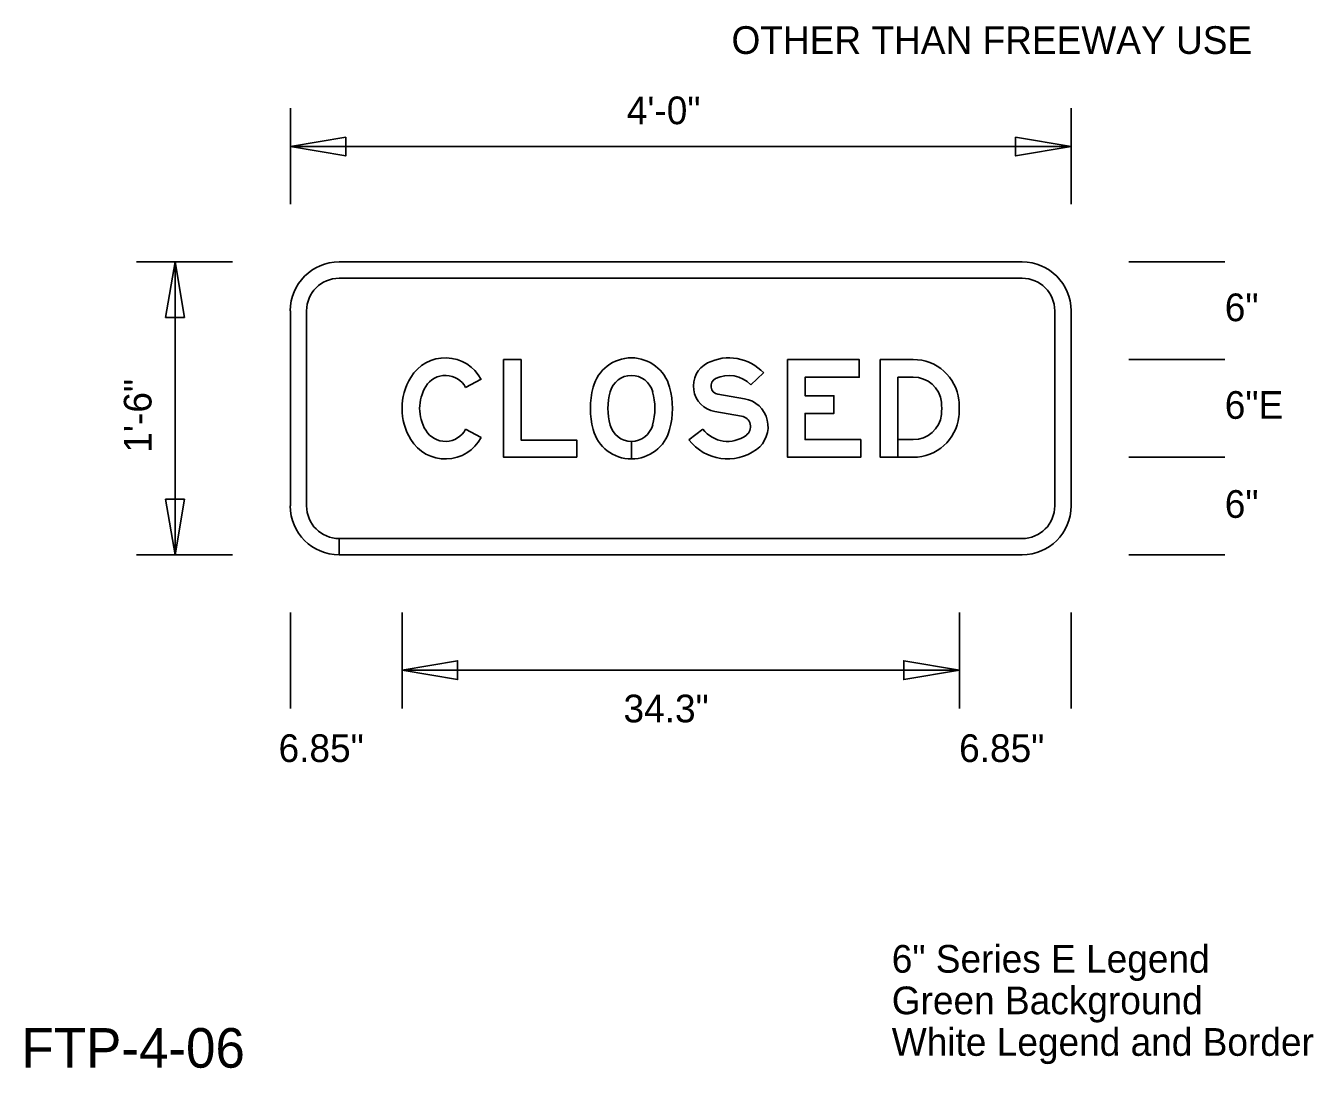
# Model space of a CAD drawing. Extents: x 0 to 770, y 0 to 495.
# Drawn here: x 584.7 to 747.4, y 356 to 487.7 of the extents above; entities that cross this region are included whole.
import ezdxf

# ---------------------------------------------------------------- set-up
doc = ezdxf.new("R2010")
doc.units = 0
for name, color, linetype in [('Dimension', 7, 'Continuous'), ('GSBWFill', 7, 'Continuous'), ('GSColorFill', 7, 'Continuous'), ('GSDims', 7, 'Continuous'), ('GSOutline', 7, 'Continuous'), ('TextStructures', 7, 'Continuous')]:
    doc.layers.add(name, color=color, linetype=linetype)

msp = doc.modelspace()

# ---------------------------------------------------------------- linework, layer by layer
at = {"layer": 'Dimension'}
for points in [[(618.12, 472.41), (625.13, 471.22), (625.13, 473.59)], [(716.78, 472.41), (709.76, 473.59), (709.76, 471.22)], [(603.55, 457.84), (602.36, 450.82), (604.74, 450.82)], [(603.55, 420.84), (604.74, 427.86), (602.36, 427.86)], [(632.24, 406.27), (639.25, 405.08), (639.25, 407.46)], [(702.66, 406.27), (695.64, 407.46), (695.64, 405.08)]]:
    msp.add_lwpolyline(points, close=True, dxfattribs=at)
at = {"layer": 'GSBWFill'}
for p, q in [((710.61, 457.84), (624.28, 457.84)), ((710.61, 457.84), (624.28, 457.84)), ((624.28, 455.78), (710.61, 455.78)), ((618.12, 451.67), (618.12, 427.01)), ((618.12, 451.67), (618.12, 427.01)), ((620.17, 427.01), (620.17, 451.67)), ((714.72, 451.67), (714.72, 427.01)), ((716.78, 427.01), (716.78, 451.67)), ((716.78, 427.01), (716.78, 451.67)), ((640.27, 441.96), (642.23, 443.01)), ((676.3, 442.3), (677.93, 443.81)), ((675.5, 440.56), (672.14, 441.12)), ((671.77, 438.94), (675.13, 438.37)), ((642.23, 435.67), (640.27, 436.71)), ((640.27, 436.71), (640.27, 436.71)), ((670.25, 436.71), (668.49, 435.36)), ((661.22, 432.96), (661.22, 435.18)), ((661.22, 435.18), (661.22, 432.96)), ((694.89, 433.17), (696.84, 433.17)), ((624.28, 420.84), (624.28, 422.89)), ((710.61, 422.89), (624.3, 422.89)), ((624.3, 422.89), (624.3, 420.84)), ((624.28, 420.84), (710.61, 420.84)), ((624.3, 420.84), (710.61, 420.84))]:
    msp.add_line(p, q, dxfattribs=at)
for points in [[(654.31, 433.17), (654.31, 435.33), (647.28, 435.33), (647.28, 445.5), (645.06, 445.5), (645.06, 433.17)], [(690.2, 435.39), (683.17, 435.39), (683.17, 438.71), (686.81, 438.71), (686.81, 440.93), (683.17, 440.93), (683.17, 443.28), (690.02, 443.28), (690.02, 445.5), (680.95, 445.5), (680.95, 433.17), (690.2, 433.17)]]:
    msp.add_lwpolyline(points, close=True, dxfattribs=at)
for points in [[(696.84, 445.5), (692.67, 445.5), (692.67, 433.17), (694.89, 433.17), (694.89, 443.28), (696.84, 443.28)], [(696.84, 435.39), (694.89, 435.39), (694.89, 433.17)]]:
    msp.add_lwpolyline(points, dxfattribs=at)
for centre, radius, start, end in [((624.28, 451.67), 6.17, 90, 180), ((624.28, 451.67), 6.17, 90, 180), ((710.61, 451.67), 6.17, 0, 90), ((710.61, 451.67), 6.17, 0, 90), ((624.28, 451.67), 4.11, 90, 180), ((710.61, 451.67), 4.11, 0, 90), ((637.71, 440.6), 5.12, 28.0265, 148.7499), ((661.22, 440.72), 5, 14.9618, 165.0382), ((672.32, 442.16), 3.27, 116.9123, 260.4087), ((673.55, 439.74), 5.98, 42.8759, 116.9123), ((639.79, 439.34), 7.55, 148.7499, 211.2501), ((637.71, 440.6), 2.9, 28.0265, 148.7499), ((661.22, 440.72), 2.78, 14.9618, 165.0382), ((672.32, 442.16), 1.05, 116.9123, 260.4087), ((673.55, 439.74), 3.76, 42.8759, 116.9123), ((639.79, 439.34), 5.33, 148.7499, 211.2501), ((666.4, 439.34), 10.36, 165.0382, 194.9618), ((666.4, 439.34), 8.14, 165.0382, 194.9618), ((656.04, 439.34), 8.14, 345.0382, 14.9618), ((656.04, 439.34), 10.36, 345.0382, 14.9618), ((674.91, 437.03), 3.58, 306.123, 80.4087), ((674.91, 437.03), 1.36, 306.123, 80.4087), ((637.71, 438.07), 2.9, 211.2501, 331.9735), ((661.22, 437.95), 5, 194.9618, 270), ((661.22, 437.95), 2.78, 194.9618, 270), ((661.22, 437.95), 2.78, 270.0127, 345.0382), ((661.22, 437.95), 5, 270.0071, 345.0382), ((673.38, 439.12), 3.95, 217.5895, 306.123), ((637.71, 438.07), 5.12, 211.2501, 331.9735), ((673.38, 439.12), 6.17, 217.5895, 306.123), ((624.28, 427.01), 6.17, 180, 270), ((624.28, 427.01), 6.17, 180, 270), ((624.28, 427.01), 4.11, 180, 270), ((710.61, 427.01), 6.17, 270, 0), ((710.61, 427.01), 4.11, 270, 0), ((710.61, 427.01), 6.17, 270, 0)]:
    msp.add_arc(centre, radius, start, end, dxfattribs=at)
for centre, major_axis, start_param, end_param in [((696.84, 439.71), (0, 5.8), 4.82584, 6.283185), ((696.84, 439.71), (0, 3.58), 4.82584, 6.283185), ((693.59, 439.34), (0, 6.84), 4.598938, 4.82584), ((693.59, 439.34), (0, 9.06), 4.598938, 4.82584), ((696.84, 438.97), (0, 3.58), 3.141593, 4.598938), ((696.84, 438.97), (0, 5.8), 3.141593, 4.598938)]:
    msp.add_ellipse(centre, major_axis=major_axis, ratio=0.999994, start_param=start_param, end_param=end_param, dxfattribs=at)
at = {"layer": 'GSColorFill'}
for p, q in [((640.27, 441.96), (642.23, 443.01)), ((676.3, 442.3), (677.93, 443.81)), ((675.5, 440.56), (672.14, 441.12)), ((671.77, 438.94), (675.13, 438.37)), ((642.23, 435.67), (640.27, 436.71)), ((640.27, 436.71), (640.27, 436.71)), ((670.25, 436.71), (668.49, 435.36)), ((661.22, 432.96), (661.22, 435.18)), ((661.22, 435.18), (661.22, 432.96)), ((694.89, 433.17), (696.84, 433.17))]:
    msp.add_line(p, q, dxfattribs=at)
for points in [[(654.31, 433.17), (654.31, 435.33), (647.28, 435.33), (647.28, 445.5), (645.06, 445.5), (645.06, 433.17)], [(690.2, 435.39), (683.17, 435.39), (683.17, 438.71), (686.81, 438.71), (686.81, 440.93), (683.17, 440.93), (683.17, 443.28), (690.02, 443.28), (690.02, 445.5), (680.95, 445.5), (680.95, 433.17), (690.2, 433.17)]]:
    msp.add_lwpolyline(points, close=True, dxfattribs=at)
for points in [[(696.84, 445.5), (692.67, 445.5), (692.67, 433.17), (694.89, 433.17), (694.89, 443.28), (696.84, 443.28)], [(696.84, 435.39), (694.89, 435.39), (694.89, 433.17)]]:
    msp.add_lwpolyline(points, dxfattribs=at)
for centre, radius, start, end in [((637.71, 440.6), 5.12, 28.0265, 148.7499), ((661.22, 440.72), 5, 14.9618, 165.0382), ((672.32, 442.16), 3.27, 116.9123, 260.4087), ((673.55, 439.74), 5.98, 42.8759, 116.9123), ((639.79, 439.34), 7.55, 148.7499, 211.2501), ((637.71, 440.6), 2.9, 28.0265, 148.7499), ((661.22, 440.72), 2.78, 14.9618, 165.0382), ((672.32, 442.16), 1.05, 116.9123, 260.4087), ((673.55, 439.74), 3.76, 42.8759, 116.9123), ((639.79, 439.34), 5.33, 148.7499, 211.2501), ((666.4, 439.34), 10.36, 165.0382, 194.9618), ((666.4, 439.34), 8.14, 165.0382, 194.9618), ((656.04, 439.34), 8.14, 345.0382, 14.9618), ((656.04, 439.34), 10.36, 345.0382, 14.9618), ((674.91, 437.03), 3.58, 306.123, 80.4087), ((674.91, 437.03), 1.36, 306.123, 80.4087), ((637.71, 438.07), 2.9, 211.2501, 331.9735), ((661.22, 437.95), 5, 194.9618, 270), ((661.22, 437.95), 2.78, 194.9618, 270), ((661.22, 437.95), 2.78, 270.0127, 345.0382), ((661.22, 437.95), 5, 270.0071, 345.0382), ((673.38, 439.12), 3.95, 217.5895, 306.123), ((637.71, 438.07), 5.12, 211.2501, 331.9735), ((673.38, 439.12), 6.17, 217.5895, 306.123)]:
    msp.add_arc(centre, radius, start, end, dxfattribs=at)
for centre, major_axis, start_param, end_param in [((696.84, 439.71), (0, 5.8), 4.82584, 6.283185), ((696.84, 439.71), (0, 3.58), 4.82584, 6.283185), ((693.59, 439.34), (0, 6.84), 4.598938, 4.82584), ((693.59, 439.34), (0, 9.06), 4.598938, 4.82584), ((696.84, 438.97), (0, 3.58), 3.141593, 4.598938), ((696.84, 438.97), (0, 5.8), 3.141593, 4.598938)]:
    msp.add_ellipse(centre, major_axis=major_axis, ratio=0.999994, start_param=start_param, end_param=end_param, dxfattribs=at)
at = {"layer": 'GSDims'}
for p, q in [((618.12, 465.12), (618.12, 477.26)), ((716.78, 465.12), (716.78, 477.26)), ((618.12, 472.41), (716.78, 472.41)), ((610.83, 457.84), (598.69, 457.84)), ((603.55, 420.84), (603.55, 457.84)), ((724.06, 457.84), (736.2, 457.84)), ((724.06, 445.5), (736.2, 445.5)), ((724.06, 445.5), (736.2, 445.5)), ((724.06, 433.17), (736.2, 433.17)), ((724.06, 433.17), (736.2, 433.17)), ((610.83, 420.84), (598.69, 420.84)), ((724.06, 420.84), (736.2, 420.84)), ((618.12, 413.55), (618.12, 401.41)), ((632.24, 413.55), (632.24, 401.41)), ((632.24, 413.55), (632.24, 401.41)), ((702.66, 413.55), (702.66, 401.41)), ((702.66, 413.55), (702.66, 401.41)), ((716.78, 413.55), (716.78, 401.41)), ((632.24, 406.27), (702.66, 406.27))]:
    msp.add_line(p, q, dxfattribs=at)
at = {"layer": 'GSOutline'}
for p, q in [((640.27, 441.96), (642.23, 443.01)), ((676.3, 442.3), (677.93, 443.81)), ((675.5, 440.56), (672.14, 441.12)), ((671.77, 438.94), (675.13, 438.37)), ((642.23, 435.67), (640.27, 436.71)), ((640.27, 436.71), (640.27, 436.71)), ((670.25, 436.71), (668.49, 435.36)), ((694.89, 435.39), (696.84, 435.39))]:
    msp.add_line(p, q, dxfattribs=at)
for points in [[(654.31, 433.17), (654.31, 435.33), (647.28, 435.33), (647.28, 445.5), (645.06, 445.5), (645.06, 433.17)], [(690.2, 435.39), (683.17, 435.39), (683.17, 438.71), (686.81, 438.71), (686.81, 440.93), (683.17, 440.93), (683.17, 443.28), (690.02, 443.28), (690.02, 445.5), (680.95, 445.5), (680.95, 433.17), (690.2, 433.17)]]:
    msp.add_lwpolyline(points, close=True, dxfattribs=at)
for points in [[(696.84, 445.5), (692.67, 445.5), (692.67, 433.17), (696.84, 433.17)], [(696.84, 443.28), (694.89, 443.28), (694.89, 435.39)]]:
    msp.add_lwpolyline(points, dxfattribs=at)
for centre, radius, start, end in [((637.71, 440.6), 5.12, 28.0265, 148.7499), ((661.22, 440.72), 5, 14.9618, 165.0382), ((672.32, 442.16), 3.27, 116.9123, 260.4087), ((673.55, 439.74), 5.98, 42.8759, 116.9123), ((639.79, 439.34), 7.55, 148.7499, 211.2501), ((637.71, 440.6), 2.9, 28.0265, 148.7499), ((661.22, 440.72), 2.78, 14.9618, 165.0382), ((672.32, 442.16), 1.05, 116.9123, 260.4087), ((673.55, 439.74), 3.76, 42.8759, 116.9123), ((639.79, 439.34), 5.33, 148.7499, 211.2501), ((666.4, 439.34), 10.36, 165.0382, 194.9618), ((666.4, 439.34), 8.14, 165.0382, 194.9618), ((656.04, 439.34), 8.14, 345.0382, 14.9618), ((656.04, 439.34), 10.36, 345.0382, 14.9618), ((674.91, 437.03), 3.58, 306.123, 80.4087), ((674.91, 437.03), 1.36, 306.123, 80.4087), ((637.71, 438.07), 2.9, 211.2501, 331.9735), ((661.22, 437.95), 5, 194.9618, 345.0382), ((661.22, 437.95), 2.78, 194.9618, 345.0382), ((673.38, 439.12), 3.95, 217.5895, 306.123), ((637.71, 438.07), 5.12, 211.2501, 331.9735), ((673.38, 439.12), 6.17, 217.5895, 306.123)]:
    msp.add_arc(centre, radius, start, end, dxfattribs=at)
for centre, major_axis, start_param, end_param in [((696.84, 439.71), (0, 5.8), 4.82584, 6.283185), ((696.84, 439.71), (0, 3.58), 4.82584, 6.283185), ((693.59, 439.34), (0, 6.84), 4.598938, 4.82584), ((693.59, 439.34), (0, 9.06), 4.598938, 4.82584), ((696.84, 438.97), (0, 3.58), 3.141593, 4.598938), ((696.84, 438.97), (0, 5.8), 3.141593, 4.598938)]:
    msp.add_ellipse(centre, major_axis=major_axis, ratio=0.999994, start_param=start_param, end_param=end_param, dxfattribs=at)

# ---------------------------------------------------------------- texts
at = {"layer": 'TextStructures'}
for s, height, p in [('OTHER THAN FREEWAY USE', 3.5, (673.87, 484.11)), ('4\'-0"', 3.5, (660.63, 475.23)), ('6"', 3.5, (736.2, 450.35)), ('6"E', 3.5, (736.2, 438.02)), ('6"', 3.5, (736.2, 425.51)), ('34.3"', 3.5, (660.22, 399.68)), ('6.85"', 3.5, (616.63, 394.67)), ('6.85"', 3.5, (702.63, 394.67)), ('6" Series E Legend', 3.5, (694.12, 368.06)), ('Green Background', 3.5, (694.12, 362.81)), ('White Legend and Border', 3.5, (694.12, 357.56)), ('FTP-4-06', 5, (584.14, 356.06))]:
    msp.add_text(s, height=height, dxfattribs=at).set_placement(p)
msp.add_text('1\'-6"', height=3.5, rotation=90, dxfattribs=at).set_placement((600.58, 433.74))

doc.saveas('drawing.dxf')
